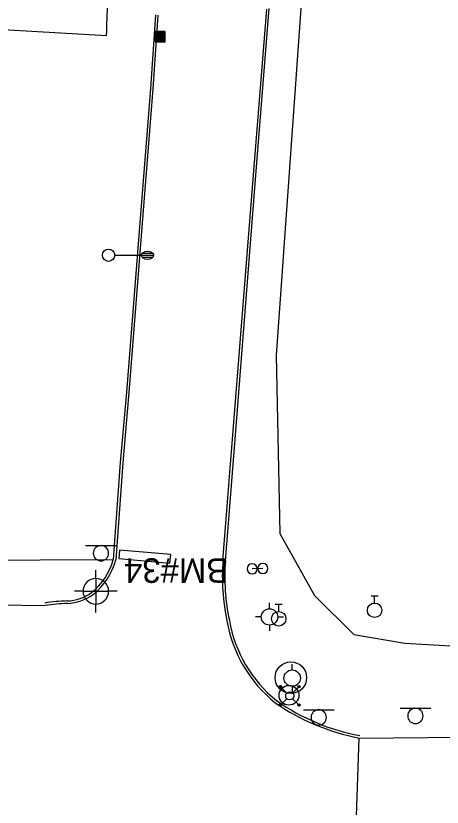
# Model space of a CAD drawing. Extents: x 2145380 to 2157287, y 139568 to 149130.
# Drawn here: x 2150976.4 to 2151080.6, y 140325.9 to 140519.3 of the extents above; entities that cross this region are included whole.
import ezdxf

# ---------------------------------------------------------------- set-up
doc = ezdxf.new("R2010")
doc.units = 0
for name, color, linetype in [('Default', 7, 'Continuous'), ('PR_PREVIOUSLY CONSTRUCTED', 7, 'Continuous'), ('SURV_Benchmark', 7, 'Continuous'), ('TOPO_Asphalt', 7, 'Continuous'), ('TOPO_Curb Back', 7, 'Continuous'), ('TOPO_Light Pole', 7, 'Continuous'), ('TOPO_Misc', 7, 'Continuous'), ('TOPO_Misc Line', 7, 'Continuous'), ('TOPO_Power Pole', 7, 'Continuous'), ('TOPO_Sidewalk', 7, 'Continuous'), ('TOPO_Sign', 7, 'Continuous'), ('TOPO_Tree', 7, 'Continuous'), ('TOPO_Wall Freestanding', 7, 'Continuous'), ('TOPO_Water Fire Hydrant', 7, 'Continuous'), ('TOPO_Water Valve', 7, 'Continuous')]:
    doc.layers.add(name, color=color, linetype=linetype)

# ---------------------------------------------------------------- blocks, each defined once
blk = doc.blocks.new('POST')
at = {"layer": 'TOPO_Misc'}
for start, end in [(90, 180), (180, 270), (360, 90), (270, 0)]:
    blk.add_arc((-0.01, 0.03), 3.16, start, end, dxfattribs=at)
blk = doc.blocks.new('FIRHYD')
at = {"layer": 'TOPO_Water Fire Hydrant'}
for p, q in [((-0.02, 10.16), (-0.03, 17.34)), ((10.16, 0.02), (17.34, 0.03)), ((-10.16, -0.02), (-17.34, -0.03)), ((0.02, -10.16), (0.03, -17.34))]:
    blk.add_line(p, q, dxfattribs=at)
blk.add_circle((0, 0), 10.16, dxfattribs=at)
blk = doc.blocks.new('LP')
at = {"layer": 'TOPO_Light Pole'}
blk.add_line((3.81, 0), (20.32, 0), dxfattribs=at)
for points in [[(20.32, 0), (27.94, 0)], [(20.32, 0), (23.5, 0)], [(20.83, 1.27), (27.43, 1.27)], [(20.83, 1.27), (23.5, 1.27)], [(23.71, 1.27), (27.43, 1.27)], [(23.71, 0), (27.94, 0)], [(20.83, -1.27), (27.43, -1.27)], [(20.83, -1.27), (23.5, -1.27)], [(23.71, -1.27), (27.43, -1.27)]]:
    blk.add_lwpolyline(points, dxfattribs=at)
blk.add_circle((0, 0), 3.81, dxfattribs=at)
blk.add_ellipse((24.13, 0), major_axis=(3.81, 0), ratio=0.666667, dxfattribs=at)
blk = doc.blocks.new('CB')
at = {"layer": 'TOPO_Misc'}
for p, q in [((-3.08, 2.99), (3.24, 2.99)), ((-3.08, 2.68), (3.24, 2.68)), ((-3.08, 2.36), (3.24, 2.36)), ((-3.08, 2.05), (3.24, 2.05)), ((-3.08, 1.73), (3.24, 1.73)), ((-3.08, 1.4), (3.24, 1.4)), ((-3.08, 1.1), (3.24, 1.1)), ((-3.08, 0.77), (3.24, 0.77)), ((-3.08, 0.46), (3.24, 0.46)), ((-3.08, 0.14), (3.24, 0.14)), ((-3.08, -0.17), (3.24, -0.17)), ((-3.08, -0.48), (3.24, -0.48)), ((-3.08, -0.8), (3.24, -0.8)), ((-3.08, -1.11), (3.26, -1.11)), ((-3.08, -1.43), (3.26, -1.43)), ((-3.08, -1.75), (3.26, -1.75)), ((-3.08, -2.07), (3.26, -2.07)), ((-3.08, -2.39), (3.26, -2.39)), ((-3.08, -2.7), (3.26, -2.7)), ((-3.08, -3.02), (3.26, -3.02))]:
    blk.add_line(p, q, dxfattribs=at)
blk.add_lwpolyline([(3.26, -3.29), (3.24, 3.05), (-3.09, 3.04), (-3.08, -3.3), (3.26, -3.29)], dxfattribs=at)
blk = doc.blocks.new('POWPOL')
at = {"layer": 'TOPO_Power Pole'}
for p, q in [((0, 10.16), (0, 17.34)), ((0, -10.16), (0, -17.34))]:
    blk.add_line(p, q, dxfattribs=at)
blk.add_circle((0, 0), 10.16, dxfattribs=at)
blk = doc.blocks.new('HIGHMAST')
at = {"layer": 'Default'}
for p, q in [((-6.44, 5.71), (-6.22, 6.22)), ((-6.22, 5.2), (-6.44, 5.71)), ((-6.31, 5.85), (-5.9, 6.28)), ((-6.16, 5.28), (-6.31, 5.85)), ((-6.25, 5.72), (-5.19, 5.62)), ((-5.58, 5.13), (-6.25, 5.72)), ((-6.22, 6.22), (-5.71, 6.44)), ((-6.22, 5.2), (-6.22, 5.2)), ((-5.71, 4.98), (-6.22, 5.2)), ((-6.21, 5.83), (-5.88, 6.16)), ((-6.09, 5.38), (-6.21, 5.83)), ((-6.15, 5.28), (-6.16, 5.28)), ((-5.72, 5.08), (-6.15, 5.28)), ((-6.09, 5.38), (-6.09, 5.38)), ((-5.62, 5.22), (-6.09, 5.38)), ((-6.08, 5.72), (-5.78, 6)), ((-5.74, 5.36), (-6.08, 5.72)), ((-6.02, 5.47), (-5.99, 5.94)), ((-6.02, 5.47), (-6.02, 5.47)), ((-5.48, 5.42), (-6.02, 5.47)), ((-5.99, 5.94), (-5.53, 5.97)), ((-5.78, 5.83), (-5.92, 5.69)), ((-5.92, 5.69), (-5.75, 5.51)), ((-5.9, 6.28), (-5.32, 6.14)), ((-5.88, 6.16), (-5.43, 6.05)), ((-5.8, 6.29), (-5.58, 5.13)), ((-5.79, 5.79), (-5.8, 6.29)), ((-5.6, 5.65), (-5.79, 5.79)), ((-5.78, 6), (-5.78, 5.83)), ((-5.77, 6.02), (-5.42, 5.63)), ((-5.75, 5.51), (-5.6, 5.65)), ((-5.42, 5.63), (-5.74, 5.36)), ((-5.28, 5.26), (-5.72, 5.08)), ((-5.71, 6.44), (-5.2, 6.22)), ((-5.2, 5.2), (-5.71, 4.98)), ((-5.26, 5.57), (-5.62, 5.22)), ((-5.53, 5.97), (-5.53, 5.96)), ((-5.52, 5.96), (-5.48, 5.42)), ((-5.43, 6.05), (-5.43, 6.05)), ((-5.41, 6.05), (-5.26, 5.57)), ((-5.32, 6.14), (-5.31, 6.13)), ((-5.3, 6.14), (-5.1, 5.7)), ((-5.1, 5.7), (-5.28, 5.26)), ((-5.2, 6.22), (-4.98, 5.71)), ((-5.2, 6.22), (-5.2, 6.22)), ((-4.98, 5.71), (-5.2, 5.2)), ((-5.2, 5.2), (-1.77, 1.77)), ((5.2, 5.2), (1.77, 1.77)), ((4.98, 5.71), (5.2, 6.22)), ((5.2, 5.2), (4.98, 5.71)), ((5.08, 5.72), (5.28, 6.15)), ((5.26, 5.28), (5.08, 5.72)), ((5.13, 5.58), (5.72, 6.25)), ((6.29, 5.8), (5.13, 5.58)), ((5.2, 6.22), (5.71, 6.44)), ((5.2, 6.22), (5.2, 6.22)), ((5.71, 4.98), (5.2, 5.2)), ((5.22, 5.62), (5.38, 6.09)), ((5.57, 5.26), (5.22, 5.62)), ((5.7, 5.1), (5.26, 5.28)), ((5.28, 6.16), (5.85, 6.31)), ((5.28, 6.15), (5.28, 6.16)), ((5.36, 5.74), (5.72, 6.08)), ((5.63, 5.42), (5.36, 5.74)), ((5.38, 6.09), (5.83, 6.21)), ((5.38, 6.09), (5.38, 6.09)), ((5.42, 5.48), (5.47, 6.02)), ((5.96, 5.52), (5.42, 5.48)), ((5.47, 6.02), (5.94, 5.99)), ((5.47, 6.02), (5.47, 6.02)), ((5.69, 5.92), (5.51, 5.75)), ((5.51, 5.75), (5.65, 5.6)), ((6.05, 5.41), (5.57, 5.26)), ((5.72, 6.25), (5.62, 5.19)), ((6.02, 5.77), (5.63, 5.42)), ((5.65, 5.6), (5.79, 5.79)), ((5.83, 5.78), (5.69, 5.92)), ((6.14, 5.3), (5.7, 5.1)), ((5.71, 6.44), (6.22, 6.22)), ((6.22, 5.2), (5.71, 4.98)), ((5.72, 6.08), (6, 5.78)), ((5.79, 5.79), (6.29, 5.8)), ((5.83, 6.21), (6.16, 5.88)), ((6, 5.78), (5.83, 5.78)), ((5.85, 6.31), (6.28, 5.9)), ((5.94, 5.99), (5.97, 5.53)), ((5.97, 5.53), (5.96, 5.53)), ((6.16, 5.88), (6.05, 5.43)), ((6.05, 5.43), (6.05, 5.43)), ((6.14, 5.32), (6.13, 5.31)), ((6.28, 5.9), (6.14, 5.32)), ((6.22, 6.22), (6.44, 5.71)), ((6.44, 5.71), (6.22, 5.2)), ((6.22, 5.2), (6.22, 5.2)), ((-5.2, -5.2), (-1.77, -1.77)), ((5.2, -5.2), (1.77, -1.77)), ((-6.44, -5.71), (-6.22, -5.2)), ((-6.22, -6.22), (-6.44, -5.71)), ((-6.29, -5.8), (-5.13, -5.58)), ((-5.79, -5.79), (-6.29, -5.8)), ((-6.28, -5.9), (-6.14, -5.32)), ((-5.85, -6.31), (-6.28, -5.9)), ((-6.22, -5.2), (-5.71, -4.98)), ((-6.22, -5.2), (-6.22, -5.2)), ((-5.71, -6.44), (-6.22, -6.22)), ((-6.16, -5.88), (-6.05, -5.43)), ((-5.83, -6.21), (-6.16, -5.88)), ((-6.14, -5.3), (-5.7, -5.1)), ((-6.14, -5.32), (-6.13, -5.31)), ((-6.05, -5.41), (-5.57, -5.26)), ((-6.05, -5.43), (-6.05, -5.43)), ((-6.02, -5.77), (-5.63, -5.42)), ((-6, -5.78), (-5.83, -5.78)), ((-5.72, -6.08), (-6, -5.78)), ((-5.97, -5.53), (-5.96, -5.53)), ((-5.94, -5.99), (-5.97, -5.53)), ((-5.96, -5.52), (-5.42, -5.48)), ((-5.47, -6.02), (-5.94, -5.99)), ((-5.28, -6.16), (-5.85, -6.31)), ((-5.83, -5.78), (-5.69, -5.92)), ((-5.38, -6.09), (-5.83, -6.21)), ((-5.65, -5.6), (-5.79, -5.79)), ((-5.72, -6.25), (-5.62, -5.19)), ((-5.13, -5.58), (-5.72, -6.25)), ((-5.36, -5.74), (-5.72, -6.08)), ((-5.71, -4.98), (-5.2, -5.2)), ((-5.2, -6.22), (-5.71, -6.44)), ((-5.7, -5.1), (-5.26, -5.28)), ((-5.69, -5.92), (-5.51, -5.75)), ((-5.51, -5.75), (-5.65, -5.6)), ((-5.63, -5.42), (-5.36, -5.74)), ((-5.57, -5.26), (-5.22, -5.62)), ((-5.42, -5.48), (-5.47, -6.02)), ((-5.47, -6.02), (-5.47, -6.02)), ((-5.22, -5.62), (-5.38, -6.09)), ((-5.38, -6.09), (-5.38, -6.09)), ((-5.08, -5.72), (-5.28, -6.15)), ((-5.28, -6.15), (-5.28, -6.16)), ((-5.26, -5.28), (-5.08, -5.72)), ((-5.2, -5.2), (-4.98, -5.71)), ((-4.98, -5.71), (-5.2, -6.22)), ((-5.2, -6.22), (-5.2, -6.22)), ((4.98, -5.71), (5.2, -5.2)), ((5.2, -6.22), (4.98, -5.71)), ((5.1, -5.7), (5.28, -5.26)), ((5.3, -6.14), (5.1, -5.7)), ((6.25, -5.72), (5.19, -5.62)), ((5.2, -5.2), (5.71, -4.98)), ((5.71, -6.44), (5.2, -6.22)), ((5.2, -6.22), (5.2, -6.22)), ((5.26, -5.57), (5.62, -5.22)), ((5.41, -6.05), (5.26, -5.57)), ((5.28, -5.26), (5.72, -5.08)), ((5.32, -6.14), (5.31, -6.13)), ((5.9, -6.28), (5.32, -6.14)), ((5.42, -5.63), (5.74, -5.36)), ((5.77, -6.02), (5.42, -5.63)), ((5.43, -6.05), (5.43, -6.05)), ((5.88, -6.16), (5.43, -6.05)), ((5.48, -5.42), (6.02, -5.47)), ((5.52, -5.96), (5.48, -5.42)), ((5.99, -5.94), (5.53, -5.97)), ((5.53, -5.97), (5.53, -5.96)), ((5.58, -5.13), (6.25, -5.72)), ((5.8, -6.29), (5.58, -5.13)), ((5.75, -5.51), (5.6, -5.65)), ((5.6, -5.65), (5.79, -5.79)), ((5.62, -5.22), (6.09, -5.38)), ((5.71, -4.98), (6.22, -5.2)), ((6.22, -6.22), (5.71, -6.44)), ((5.72, -5.08), (6.15, -5.28)), ((5.74, -5.36), (6.08, -5.72)), ((5.92, -5.69), (5.75, -5.51)), ((5.78, -5.83), (5.92, -5.69)), ((6.08, -5.72), (5.78, -6)), ((5.78, -6), (5.78, -5.83)), ((5.79, -5.79), (5.8, -6.29)), ((6.21, -5.83), (5.88, -6.16)), ((6.31, -5.85), (5.9, -6.28)), ((6.02, -5.47), (5.99, -5.94)), ((6.02, -5.47), (6.02, -5.47)), ((6.09, -5.38), (6.21, -5.83)), ((6.09, -5.38), (6.09, -5.38)), ((6.15, -5.28), (6.16, -5.28)), ((6.16, -5.28), (6.31, -5.85)), ((6.22, -5.2), (6.22, -5.2)), ((6.22, -5.2), (6.44, -5.71)), ((6.44, -5.71), (6.22, -6.22))]:
    blk.add_line(p, q, dxfattribs=at)
for centre, radius in [((-0.45, 0.37), 6.15), ((0, 0), 2.5), ((0, 0), 2.5), ((0, 0), 2.5), ((0, 0), 2.5)]:
    blk.add_circle(centre, radius, dxfattribs=at)
blk = doc.blocks.new('WATVAL')
at = {"layer": 'Default'}
for p, q in [((-2.25, 9), (2.25, 9)), ((0, 4.5), (0, 9))]:
    blk.add_line(p, q, dxfattribs=at)
blk.add_circle((0, 0), 4.5, dxfattribs=at)
blk = doc.blocks.new('BM')
at = {"layer": 'SURV_Benchmark'}
for p, q in [((0, 2.49), (0, 4.15)), ((-2.49, 0), (-4.16, 0)), ((4.16, 0), (2.49, 0)), ((0, -4.16), (0, -2.49))]:
    blk.add_line(p, q, dxfattribs=at)
for points in [[(0, 2.49), (0, 2.49), (0, 0), (2.49, 0), (2.49, 0), (2.49, 0)], [(0, 2.49), (0, 2.49), (0, 0), (2.49, 0), (2.49, 0), (2.49, 0), (2.49, 0)], [(-2.5, 0), (-2.49, 0), (0, 0), (0, -2.49), (0, -2.49)], [(-2.5, 0), (-2.49, 0), (0, 0), (0, -2.49), (0, -2.49)]]:
    blk.add_lwpolyline(points, dxfattribs=at)
for start, end in [(90.0638, 180.0068), (0.0638, 90.0068), (0.0638, 90.0068), (180.0638, 270.0068), (180.0638, 270.0068), (269.9472, 359.9927)]:
    blk.add_arc((0, 0), 2.5, start, end, dxfattribs=at)

msp = doc.modelspace()

# ---------------------------------------------------------------- linework, layer by layer
at = {"layer": 'PR_PREVIOUSLY CONSTRUCTED'}
msp.add_lwpolyline([(2150911.68, 140519.46), (2150913.66, 140519.35), (2150913.67, 140519.35), (2150913.68, 140519.35), (2150917.01, 140519.16), (2150998.55, 140514.49), (2150998.61, 140515.48), (2150998.65, 140516.48), (2150998.68, 140517.48), (2150998.71, 140518.48), (2150998.74, 140519.48), (2150998.77, 140520.48), (2150998.8, 140521.48), (2150998.82, 140522.48), (2150998.85, 140523.48), (2151004.39, 140523.81)], dxfattribs=at)
at = {"layer": 'TOPO_Asphalt'}
msp.add_line((2151060.21, 140342.83), (2151059.4, 140316.72), dxfattribs=at)
for points in [[(2150983.56, 140375.19), (2150979.3, 140375.09), (2150976.4, 140375.25)], [(2151060.35, 140342.81), (2151085.48, 140343.02), (2151124.03, 140343.6), (2151177.83, 140344.58), (2151232.54, 140344.63), (2151291.1, 140344.74), (2151351.87, 140345.23), (2151401.83, 140345.98), (2151448.94, 140346.84)]]:
    msp.add_lwpolyline(points, dxfattribs=at)
at = {"layer": 'TOPO_Curb Back'}
for points in [[(2151027.02, 140386.12), (2151029.79, 140420.98), (2151034.38, 140479.32), (2151037.72, 140520.91)], [(2151027.62, 140386.07), (2151030.38, 140420.93), (2151034.98, 140479.27), (2151038.33, 140521.04)], [(2151010.5, 140519.48), (2151009.28, 140501.49), (2151006.92, 140471.76), (2151003.42, 140427.3), (2151001.94, 140410.12), (2151000.21, 140386.42)], [(2151011.1, 140519.43), (2151009.88, 140501.45), (2151007.51, 140471.71), (2151004.02, 140427.26), (2151002.53, 140410.08), (2151000.8, 140386.32)], [(2150976.4, 140375.25), (2150964.33, 140375.12), (2150943.87, 140375.16), (2150932.91, 140375.05), (2150899.53, 140374.5), (2150856.89, 140374.27), (2150804.09, 140373.83), (2150767.07, 140373.49), (2150736.47, 140373.31), (2150723.96, 140373.02)]]:
    msp.add_lwpolyline(points, dxfattribs=at)
for centre, radius, start, end in [((2150985.12, 140390.56), 15.65, 308.7827, 344.6712), ((2150985.12, 140390.56), 16.25, 308.7278, 344.8801), ((2151077.83, 140382.19), 50.96, 175.5718, 192.122), ((2151077.83, 140382.19), 50.36, 175.5725, 192.1366), ((2150988.51, 140387.24), 10.95, 272.4765, 305.7985), ((2150988.51, 140387.24), 11.55, 272.4389, 305.8763), ((2150989.66, 140339.23), 37.08, 91.0452, 99.629), ((2150989.66, 140339.22), 36.48, 91.0339, 99.629), ((2151060.22, 140376.94), 32.67, 189.6133, 231.3131), ((2151060.22, 140376.94), 32.07, 189.59, 231.2766), ((2151070.28, 140395.25), 52.77, 235.1913, 259.2714), ((2151070.28, 140395.25), 53.37, 235.1695, 259.2709)]:
    msp.add_arc(centre, radius, start, end, dxfattribs=at)
at = {"layer": 'TOPO_Misc Line'}
msp.add_lwpolyline([(2151014.26, 140387.63), (2151001.73, 140388.75), (2151001.55, 140386.7), (2151014.08, 140385.58)], close=True, dxfattribs=at)
at = {"layer": 'TOPO_Sidewalk'}
msp.add_lwpolyline([(2150932.81, 140386.91), (2150934.83, 140387.15), (2150934.94, 140386.38), (2150964.51, 140386.29), (2151000.21, 140386.42)], dxfattribs=at)
at = {"layer": 'TOPO_Sign'}
for points in [[(2150993.46, 140389.82), (2151000.95, 140389.83)], [(2150997.21, 140389.82), (2150997.21, 140389.82)], [(2150995.34, 140387.96), (2150995.34, 140387.96)], [(2150999.08, 140387.96), (2150999.08, 140387.96)], [(2150997.21, 140386.09), (2150997.21, 140386.09)], [(2151036.79, 140384.21), (2151034.18, 140384.15)], [(2151070.31, 140350.09), (2151077.8, 140350.09)], [(2151074.06, 140350.09), (2151074.06, 140350.09)], [(2151046.68, 140349.73), (2151054.18, 140349.73)], [(2151050.43, 140349.73), (2151050.43, 140349.73)], [(2151072.19, 140348.22), (2151072.19, 140348.22)], [(2151075.92, 140348.22), (2151075.92, 140348.22)], [(2151048.57, 140347.86), (2151048.57, 140347.86)], [(2151050.43, 140345.99), (2151050.43, 140345.99)], [(2151052.3, 140347.86), (2151052.3, 140347.86)], [(2151074.06, 140346.35), (2151074.06, 140346.35)]]:
    msp.add_lwpolyline(points, dxfattribs=at)
for centre, start, end in [((2150997.21, 140387.96), 90, 180), ((2150997.21, 140387.96), 360, 90), ((2150997.21, 140387.96), 180, 270), ((2150997.21, 140387.96), 270, 0), ((2151074.06, 140348.22), 90, 180), ((2151074.06, 140348.22), 360, 90), ((2151050.43, 140347.86), 90, 180), ((2151050.43, 140347.86), 360, 90), ((2151074.06, 140348.22), 180, 270), ((2151074.06, 140348.22), 270, 0), ((2151050.43, 140347.86), 180, 270), ((2151050.43, 140347.86), 270, 0)]:
    msp.add_arc(centre, 1.87, start, end, dxfattribs=at)
at = {"layer": 'TOPO_Tree'}
msp.add_lwpolyline([(2151059.56, 140742.95), (2151055.53, 140643.54), (2151048.16, 140550.89), (2151040.01, 140436.32), (2151040.92, 140392.83), (2151049.39, 140377.64), (2151059.03, 140368.1), (2151071.47, 140366.03), (2151088.27, 140365.01), (2151124.1, 140363.67), (2151147.58, 140357.94), (2151185.1, 140354.06), (2151257.45, 140355.85), (2151360.13, 140352.59), (2151426.51, 140354.79), (2151448.86, 140355.58)], dxfattribs=at)
at = {"layer": 'TOPO_Wall Freestanding'}
msp.add_circle((2151043.62, 140357.58), 3.86, dxfattribs=at)

# ---------------------------------------------------------------- block references
at = {"layer": 'SURV_Benchmark', "xscale": 1.25, "yscale": 1.25}
msp.add_blockref('BM', (2150995.95, 140378.68), dxfattribs=at)
at = {"layer": 'TOPO_Light Pole', "xscale": 0.39370000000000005, "yscale": 0.3937000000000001}
for name, p in [('LP', (2150999.06, 140460.77)), ('HIGHMAST', (2151043.34, 140353.12))]:
    msp.add_blockref(name, p, dxfattribs=at)
at = {"layer": 'TOPO_Misc', "xscale": 0.39370000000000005, "yscale": 0.3937000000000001}
for name, p in [('CB', (2151011.65, 140514.2)), ('POST', (2151034.18, 140384.15)), ('POST', (2151036.79, 140384.21))]:
    msp.add_blockref(name, p, dxfattribs=at)
at = {"layer": 'TOPO_Power Pole', "xscale": 0.19685000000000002, "yscale": 0.19685000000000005}
msp.add_blockref('POWPOL', (2151043.94, 140357.45), dxfattribs=at)
at = {"layer": 'TOPO_Water Fire Hydrant', "xscale": 0.19685000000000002, "yscale": 0.19685000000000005}
msp.add_blockref('FIRHYD', (2151038.4, 140372.41), dxfattribs=at)
at = {"layer": 'TOPO_Water Valve', "xscale": 0.39370000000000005, "yscale": 0.3937000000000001}
for p in [(2151064.1, 140374.03), (2151040.65, 140371.96)]:
    msp.add_blockref('WATVAL', p, dxfattribs=at)

# ---------------------------------------------------------------- texts
at = {"layer": 'SURV_Benchmark'}
msp.add_text('BM#34', height=6, rotation=180, dxfattribs=at).set_placement((2151028.28, 140386.73))

doc.saveas('drawing.dxf')
